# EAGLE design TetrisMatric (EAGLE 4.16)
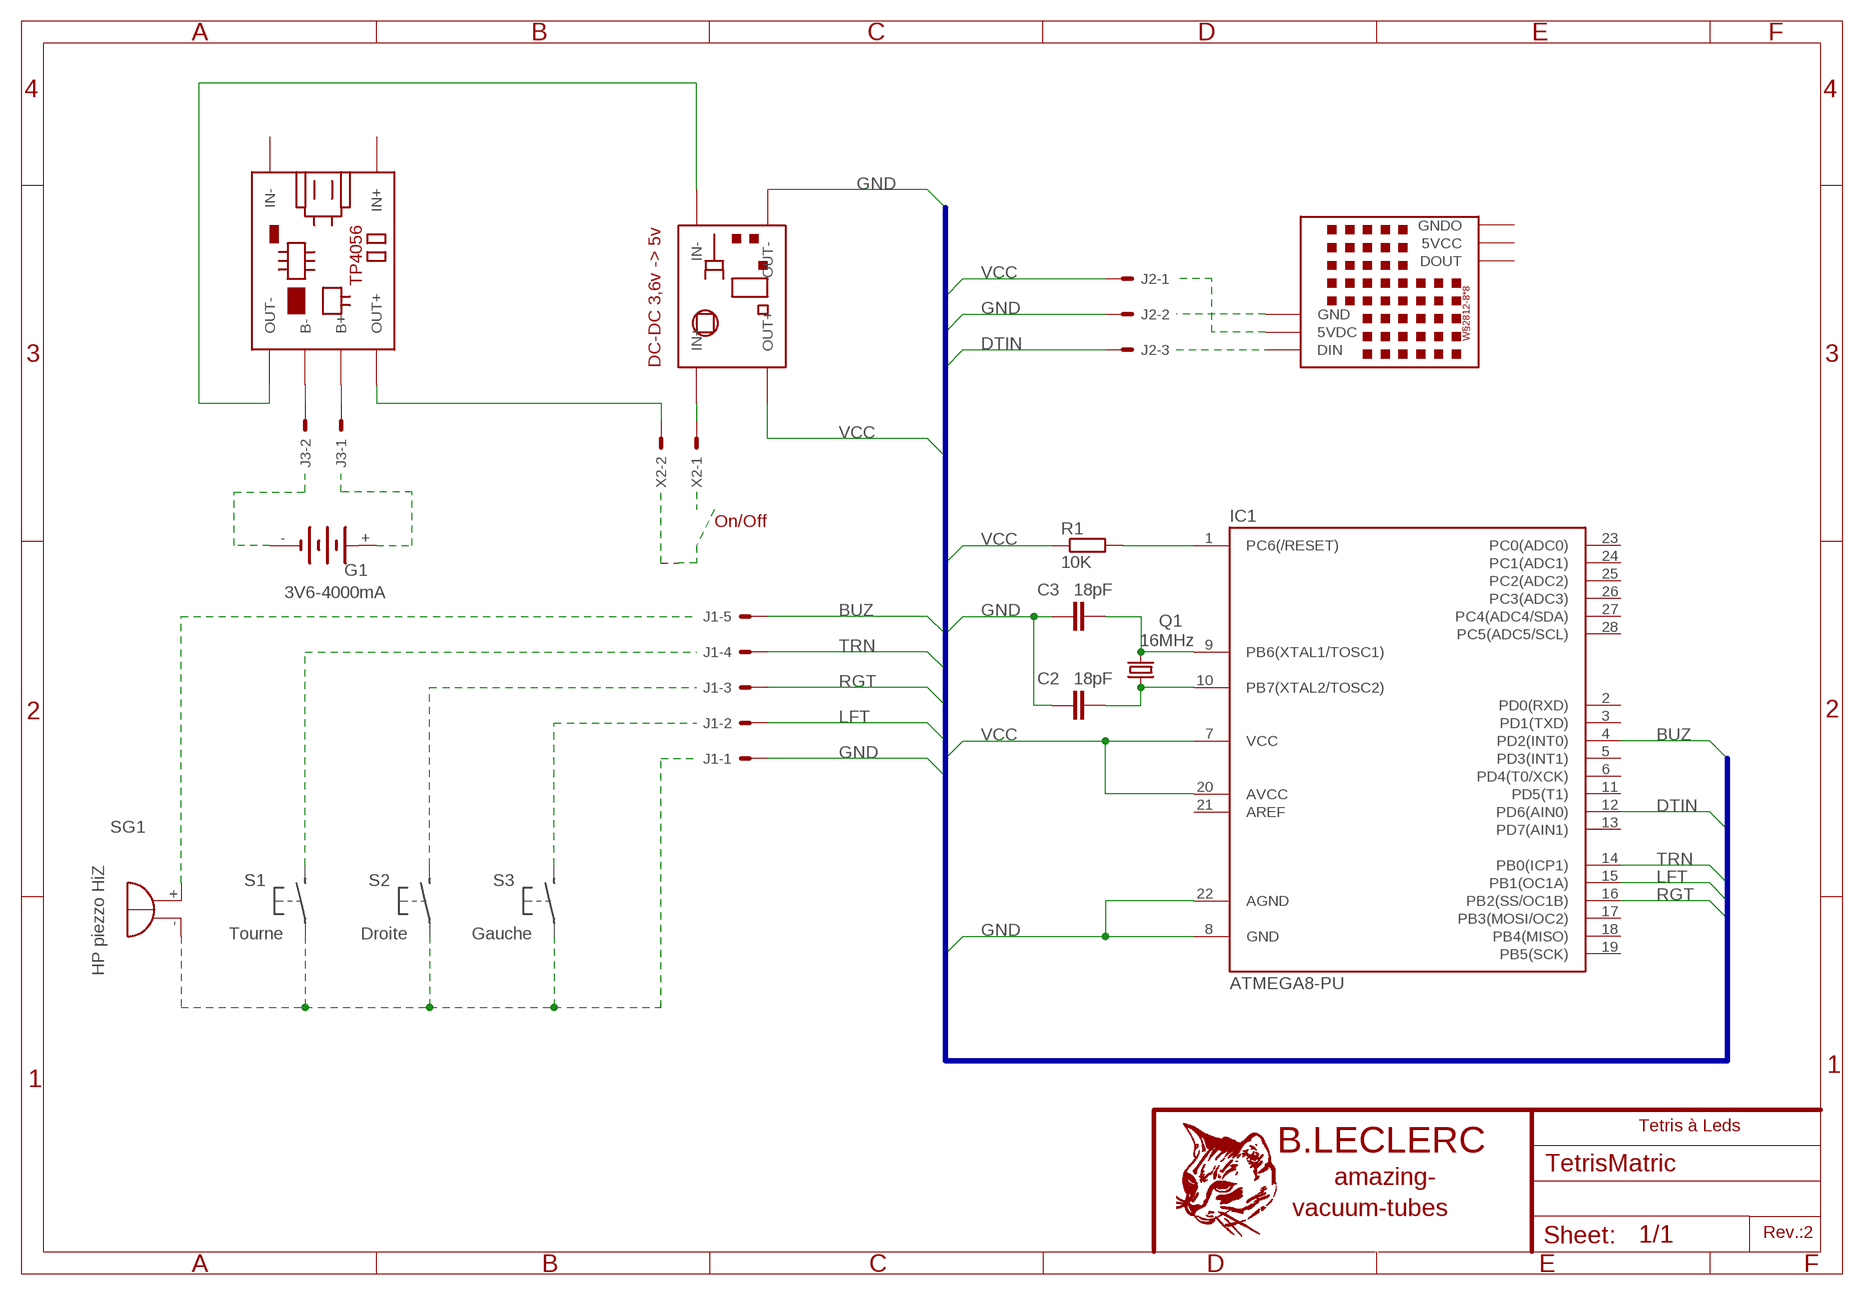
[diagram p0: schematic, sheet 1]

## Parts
C2  18pF  C-EU025_050-025X075  [C025_050-025X075]
C3  18pF  C-EU025_050-025X075  [C025_050-025X075]
G1  3V6-4000mA  3V11R  [3V11R]
IC1  ATMEGA8-PU  [DIL28-3]
J1  22-27-2051-05  [6410-05]
J2  22-27-2031-03  [6410-03]
J3  22-27-2021-02  [6410-02]
Q1  16MHz  CRYTALHC49S  [HC49/S]
R1  10K  R-EU_0207/12  [0207/12]
SG1  HP piezzo HiZ  F/QMBIII  [F/QMBIII]
U$2  DC-DC_BOOST  [DC-DC_BOOST]
U$3  64_LED_PANEL_2812-88  [64_LED_PANEL_2812-8*8]
U$4  CHARGEUR_ION-LI  [CHARGEUR_ION-LI]
X2  22-23-2021  [22-23-2021]

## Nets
BUZ: IC1.4(PD2(INT0)) J1.5
DTIN: IC1.12(PD6(AIN0)) J2.3
GND: C2.1 C3.1 IC1.8(GND) IC1.22(AGND) J1.1 J2.2 U$2.OUT-
LFT: IC1.15(PB1(OC1A)) J1.2
N$4: G1.-
N$5: G1.+
N$6: U$3.DIN
N$7: U$3.5VDC
N$8: U$3.GND
N$9: IC1.1(PC6(/RESET)) R1.2
N$11: C3.2 IC1.9(PB6(XTAL1/TOSC1)) Q1.2
N$12: C2.2 IC1.10(PB7(XTAL2/TOSC2)) Q1.1
N$13: J3.2 U$4.B-
N$14: SG1.+(-)
N$15: J3.1 U$4.B+
N$16: U$2.IN+ X2.1
N$17: U$4.OUT+ X2.2
N$19: U$2.IN- U$4.OUT-
N$36: SG1.-(+)
RGT: IC1.16(PB2(SS/OC1B)) J1.3
TRN: IC1.14(PB0(ICP1)) J1.4
VCC: IC1.7(VCC) IC1.20(AVCC) J2.1 R1.1 U$2.OUT+
Unconnected: IC1.2(PD0(RXD)) IC1.3(PD1(TXD)) IC1.5(PD3(INT1)) IC1.6(PD4(T0/XCK)) IC1.11(PD5(T1)) IC1.13(PD7(AIN1)) IC1.17(PB3(MOSI/OC2)) IC1.18(PB4(MISO)) IC1.19(PB5(SCK)) IC1.21(AREF) IC1.23(PC0(ADC0)) IC1.24(PC1(ADC1)) IC1.25(PC2(ADC2)) IC1.26(PC3(ADC3)) IC1.27(PC4(ADC4/SDA)) IC1.28(PC5(ADC5/SCL)) U$3.DOUT

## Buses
B$1

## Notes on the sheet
- On/Off
- Tetris à Leds
- Rev.:2

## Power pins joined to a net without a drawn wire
5VCC: U$3.5VCC
GNDO: U$3.GNDO
IN+: U$4.IN+
IN-: U$4.IN-

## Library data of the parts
C2 C3 = rcl:C-EU: CAPACITOR, European symbol
G1 = battery:3V11R: NC ACCU Varta
IC1 = atmega8:ATMEGA8-PU
J1 = con-molex:22-?-05: CONNECTOR wire to board 2.54 mm (.1 inch) pitch header
J2 = con-molex:22-?-03: CONNECTOR wire to board 2.54 mm (.1 inch) pitch header
J3 = con-molex:22-?-02: CONNECTOR
Q1 = crystal:CRYTAL: CRYSTAL
R1 = rcl:R-EU_: RESISTOR, European symbol
SG1 = buzzer:F/QMBIII: BUZZER
U$2 = Arduino:DC-DC_BOOST
U$3 = Arduino:64_LED_PANEL_2812-8*8
U$4 = Arduino:CHARGEUR_ION-LI
X2 = con-molex:22-23-2021: .100" (2.54mm) Center Header - 2 Pin

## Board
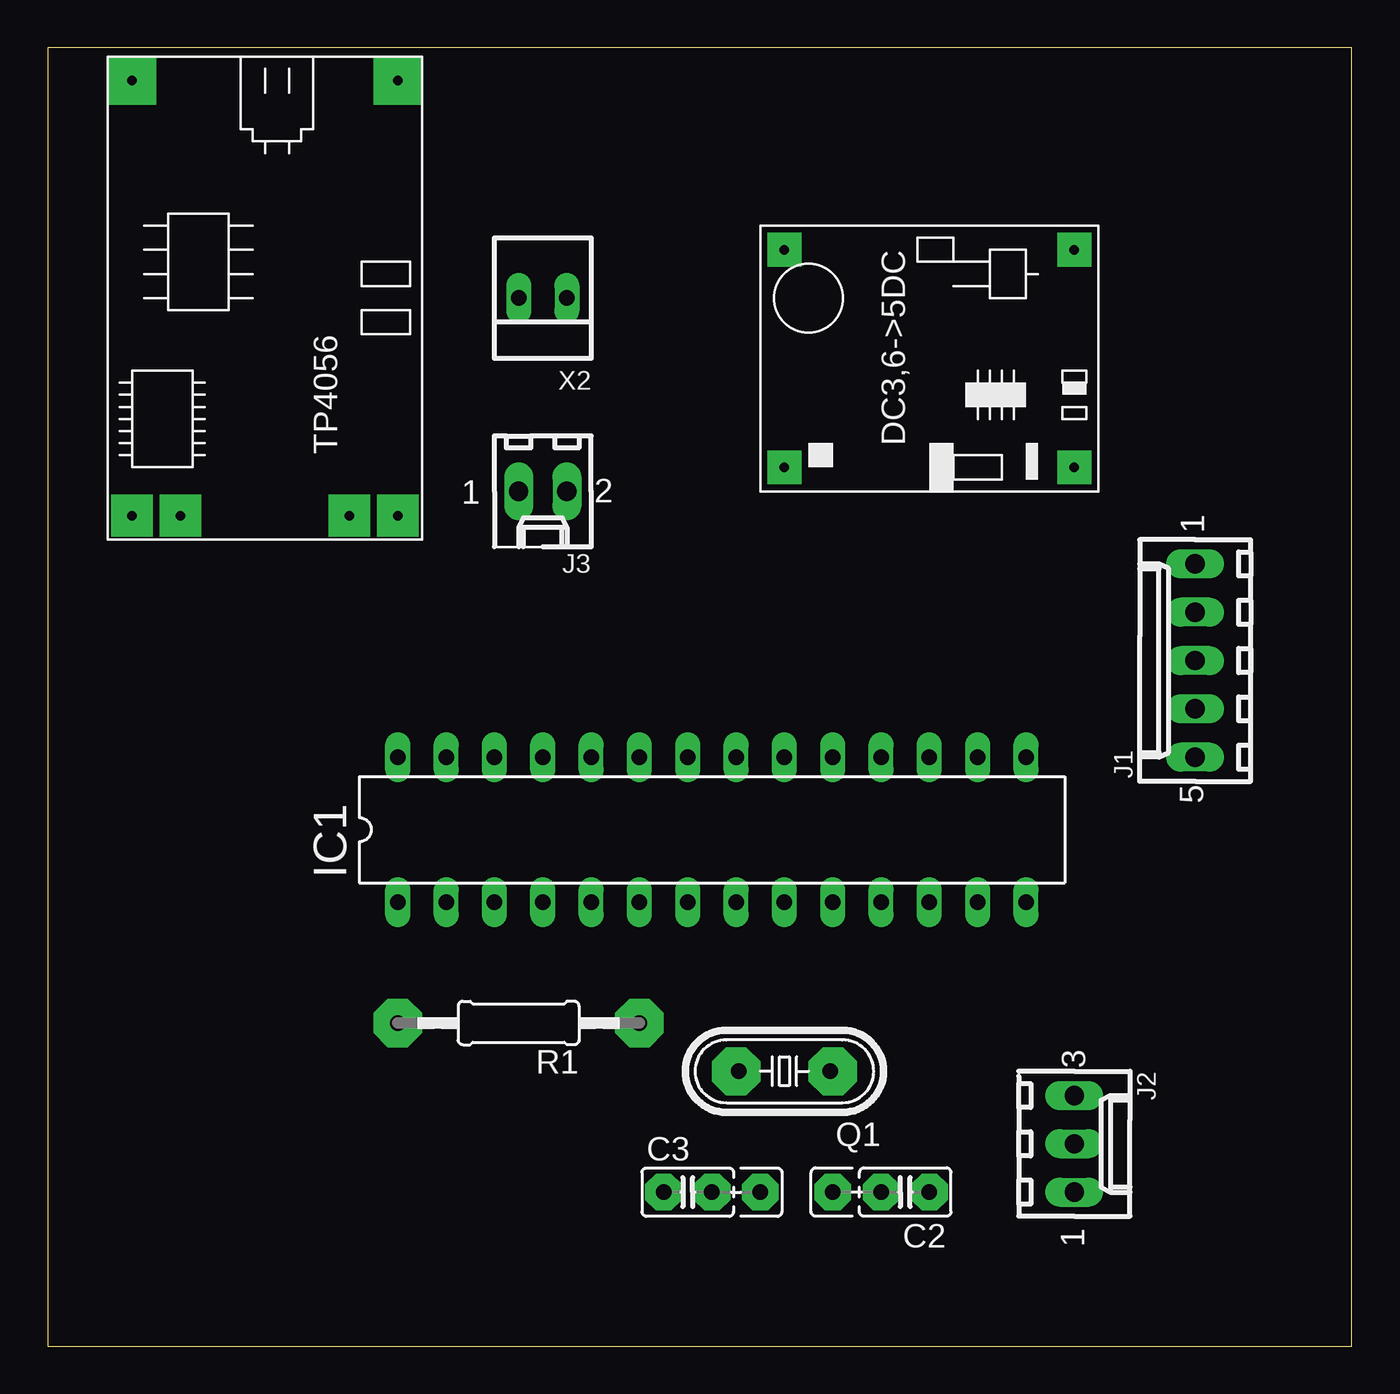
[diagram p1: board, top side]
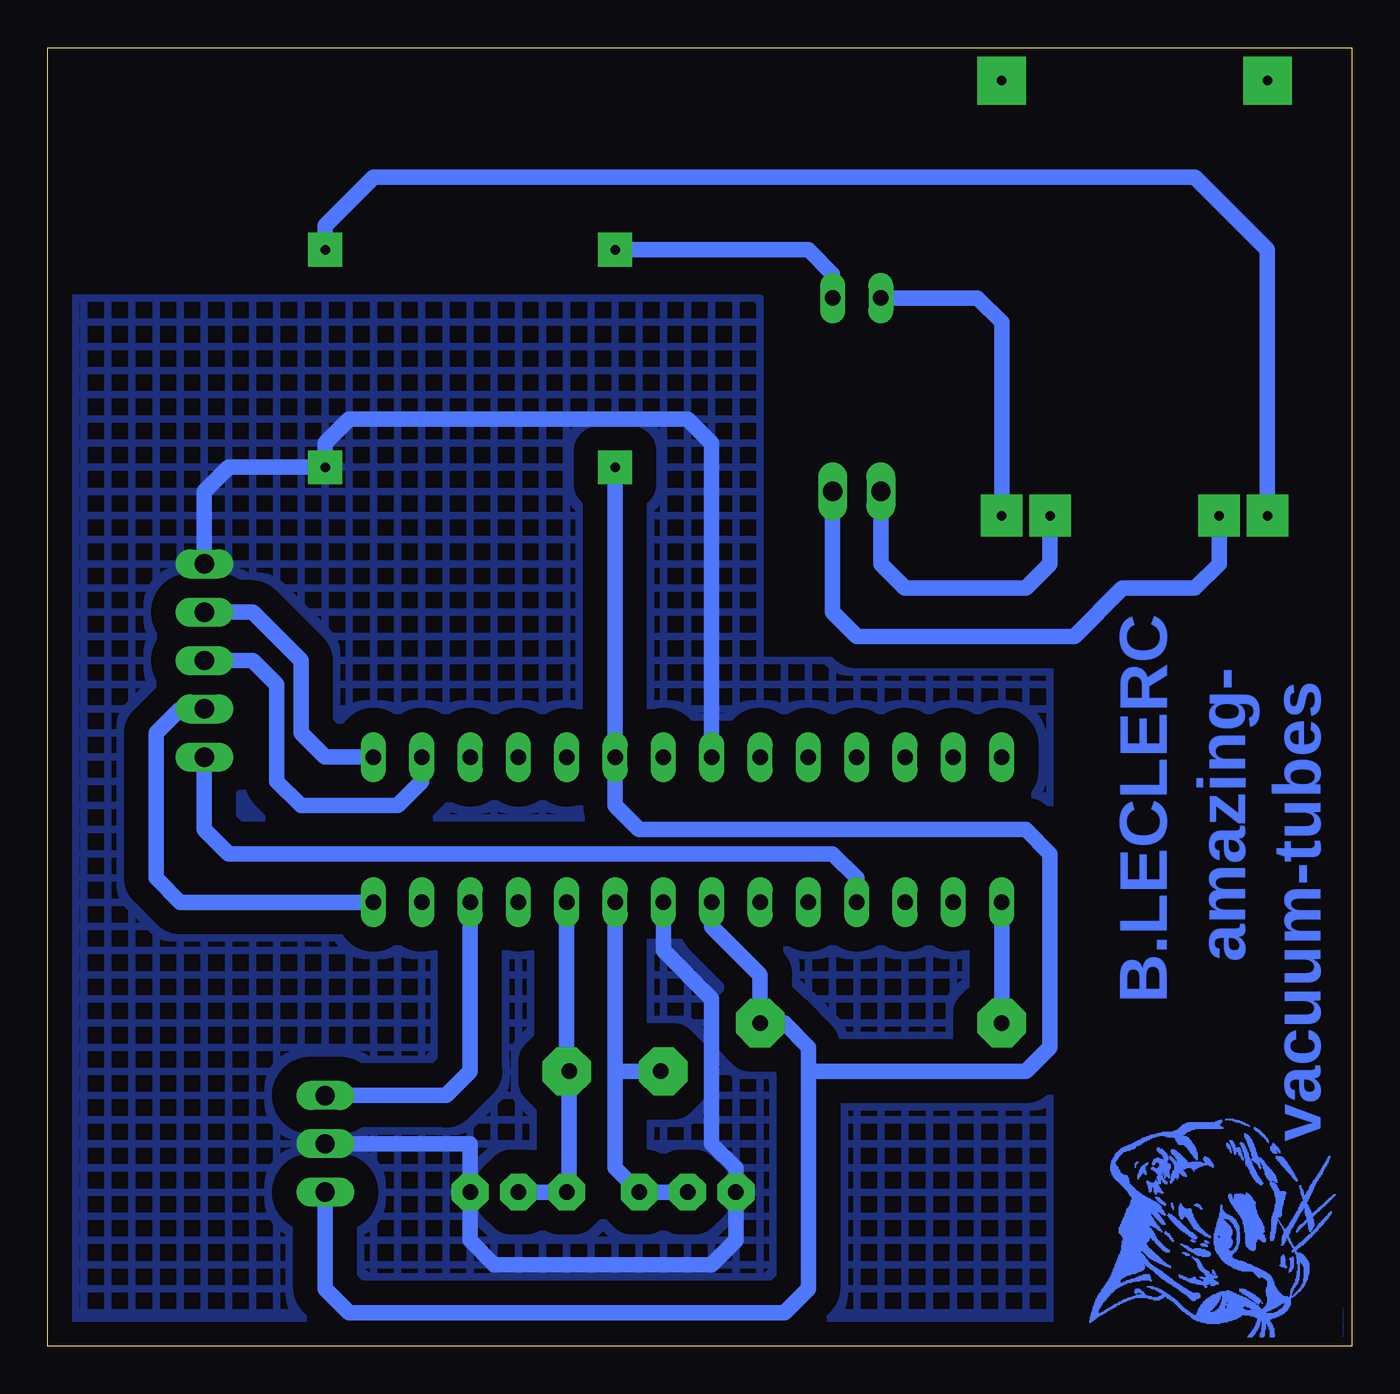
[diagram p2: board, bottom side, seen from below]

Size 68.56 x 68.25 mm. Coordinates in mm from the lower left corner, seen from the top.
Outline: 0,0 68.56,0 68.56,68.25 0,68.25 0,0
Copper layers (1*16): Top 0.035mm / dielectric 1.5mm / Bottom 0.035mm
Design rules "default": minimum track width 10mil, minimum drill 24mil, track to track 8mil, track to pad 8mil, pad to pad 8mil, via to via 8mil, smd to smd 8mil, copper to edge 40mil, drill to drill 8mil, minimum pad ring 10mil, minimum via ring 8mil, stop-mask expansion 4mil, vias tented up to drill 0mil, thermal gap 10mil

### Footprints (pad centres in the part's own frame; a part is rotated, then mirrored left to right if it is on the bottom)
C025_050-025X075 = drill 0.813 octagon: 1 -1.27,0; 2 1.27,0; 3 3.81,0
3V11R = drill 1.118 pad 2.54 octagon: + -5.08,0; - 5.08,0
DIL28-3 = drill 0.813 long: 1 -16.51,-3.81; 2 -13.97,-3.81; 3 -11.43,-3.81; 4 -8.89,-3.81; 5 -6.35,-3.81; 6 -3.81,-3.81; 7 -1.27,-3.81; 8 1.27,-3.81; 9 3.81,-3.81; 10 6.35,-3.81; 11 8.89,-3.81; 12 11.43,-3.81; 13 13.97,-3.81; 14 16.51,-3.81; 15 16.51,3.81; 16 13.97,3.81; 17 11.43,3.81; 18 8.89,3.81; 19 6.35,3.81; 20 3.81,3.81; 21 1.27,3.81; 22 -1.27,3.81; 23 -3.81,3.81; 24 -6.35,3.81; 25 -8.89,3.81; 26 -11.43,3.81; 27 -13.97,3.81; 28 -16.51,3.81
6410-05 = drill 1.016 long: 1 5.08,0; 2 2.54,0; 3 0,0; 4 -2.54,0; 5 -5.08,0
6410-03 = drill 1.016 long: 1 2.54,0; 2 0,0; 3 -2.54,0
6410-02 = drill 1.016 long: 1 1.27,0; 2 -1.27,0
HC49/S = drill 0.813 round: 1 -2.413,0; 2 2.413,0
0207/12 = drill 0.813 octagon: 1 -6.35,0; 2 6.35,0
F/QMBIII = drill 0.914 pad 2.159 octagon: + 3.251,0; - -3.251,0
DC-DC_BOOST = drill 0.5 pad 1.778 square: IN+ 0,0; IN- 0,15.24; OUT+ 11.43,0; OUT- 11.43,15.24
64_LED_PANEL_2812-8*8 = drill 0.5 pad 1.93 long: 5VCC 13.97,0; 5VDC 0,0; DIN 0,2.54; DOUT 13.97,2.54; GND 0,-2.54; GNDO 13.97,-2.54
CHARGEUR_ION-LI = drill 0.5 pad 2.184 square: B+ 24.13,12.7; B- 24.13,3.81; OUT+ 24.13,15.24; OUT- 24.13,1.27 | drill 0.5 pad 2.54 square: IN+ 1.27,15.24; IN- 1.27,1.27
22-23-2021 = drill 0.813 long: 1 -1.27,0; 2 1.27,0

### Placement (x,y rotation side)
C2  45.08,8.09 180 top
C3  33.65,8.09 0 top
G1  not placed on the board
IC1  34.92,27.14 0 top
J1  60.32,36.03 90 top
J2  53.97,10.63 270 top
J3  26.03,44.92 180 top
Q1  38.73,14.44 180 top
R1  24.76,16.98 180 top
SG1  not placed on the board
U$2  38.73,57.62 270 top
U$3  not placed on the board
U$4  3.17,67.78 270 top
U$5  [CHAT1]  0.63,0.47 90 bottom
X2  26.03,55.08 180 top

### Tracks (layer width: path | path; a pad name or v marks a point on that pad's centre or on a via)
BUZ
  Bottom 0.813: IC1.4 26.03,24.6 27.3,25.87 59.05,25.87 60.32,27.14 J1.5
DTIN
  Bottom 0.813: IC1.12 46.35,14.44 47.62,13.17 J2.3
GND  (via drill 0.5 pad 1.27, 0.5 pad 1.93)
  Bottom 0.813: J1.1 60.32,44.92 59.05,46.19 U$2.OUT- 53.97,47.46 52.7,48.73 34.92,48.73 33.65,47.46 IC1.22 | IC1.8 36.19,20.79 33.65,18.25 33.65,10.63 32.38,9.36 C3.1 32.38,5.55 33.65,4.28 45.08,4.28 46.35,5.55 C2.1 46.35,10.63 J2.2
  other vias: 60.32,41.11 53.97,10.63 32.38,8.09 46.35,8.09
  pour Bottom (isolate 1.27, no thermals, hatched): 15.87,0.47 15.87,36.03 31.11,36.03 31.11,55.08 67.94,55.08 67.94,0.47
LFT
  Bottom 0.813: J1.2 57.78,38.57 55.24,36.03 55.24,32.22 53.97,30.95 IC1.15
N$9
  Bottom 0.813: R1.2 IC1.1
N$11
  Bottom 0.813: 38.73,14.44 38.73,9.36 37.46,8.09 C3.2 | 38.73,14.44 IC1.9 | 38.73,14.44 Q1.2
N$12
  Bottom 0.813: IC1.10 41.27,14.44 Q1.1 41.14,8.22 41.27,8.09 C2.2
N$13
  Bottom 0.813: U$4.B- 6.98,41.11 8.25,39.84 12.06,39.84 14.6,37.3 26.03,37.3 27.3,38.57 J3.2
N$15
  Bottom 0.813: U$4.B+ 15.87,41.11 17.14,39.84 23.49,39.84 24.76,41.11 J3.1
N$16
  Bottom 0.813: U$2.IN+ 28.57,57.62 27.3,56.35 X2.1
N$17
  Bottom 0.813: U$4.OUT+ 18.41,53.81 19.68,55.08 X2.2
N$19
  Bottom 0.813: U$4.OUT- 4.44,57.62 8.25,61.43 51.43,61.43 53.97,58.89 U$2.IN-
N$22  (via drill 0.5 pad 2.54)
  other vias: 18.41,16.98
N$24  (via drill 0.5 pad 2.54)
  other vias: 31.11,16.98
N$25  (via drill 0.5 pad 2.54)
  other vias: 36.19,14.44
N$26  (via drill 0.5 pad 2.54)
  other vias: 41.27,14.44
N$28  (via drill 0.5 pad 1.93)
  other vias: 34.92,8.09
N$29  (via drill 0.5 pad 1.93)
  other vias: 37.46,8.09
N$30  (via drill 0.5 pad 1.93)
  other vias: 41.27,8.09
N$31  (via drill 0.5 pad 1.93)
  other vias: 43.81,8.09
N$33  (via drill 0.5 pad 1.27)
  other vias: 20.95,23.33
N$34  (via drill 0.5 pad 1.27)
  other vias: 60.32,38.57
N$35  (via drill 0.5 pad 1.27)
  other vias: 60.32,36.03
N$37  (via drill 0.5 pad 1.27)
  other vias: 60.32,33.49
N$38  (via drill 0.5 pad 1.27)
  other vias: 60.32,30.95
N$40  (via drill 0.5 pad 1.27)
  other vias: 53.97,13.17
N$41  (via drill 0.5 pad 1.27)
  other vias: 23.49,23.33
N$42  (via drill 0.5 pad 1.27)
  other vias: 53.97,8.09
N$43  (via drill 0.5 pad 1.27)
  other vias: 24.76,55.08
N$44  (via drill 0.5 pad 1.27)
  other vias: 24.76,44.92
N$45  (via drill 0.5 pad 1.27)
  other vias: 27.3,55.08
N$46  (via drill 0.5 pad 1.27)
  other vias: 27.3,44.92
N$47  (via drill 0.5 pad 1.27)
  other vias: 31.11,23.33
N$48  (via drill 0.5 pad 1.27)
  other vias: 33.65,23.33
N$49  (via drill 0.5 pad 1.27)
  other vias: 41.27,23.33
N$50  (via drill 0.5 pad 1.27)
  other vias: 46.35,23.33
N$51  (via drill 0.5 pad 1.27)
  other vias: 51.43,23.33
N$52  (via drill 0.5 pad 1.27)
  other vias: 48.89,30.95
N$53  (via drill 0.5 pad 1.27)
  other vias: 43.81,30.95
N$54  (via drill 0.5 pad 1.27)
  other vias: 38.73,30.95
N$55  (via drill 0.5 pad 1.27)
  other vias: 36.19,30.95
N$56  (via drill 0.5 pad 1.27)
  other vias: 33.65,30.95
N$57  (via drill 0.5 pad 1.27)
  other vias: 41.27,30.95
N$58  (via drill 0.5 pad 1.27)
  other vias: 46.35,30.95
N$59  (via drill 0.5 pad 1.27)
  other vias: 51.43,30.95
N$60  (via drill 0.5 pad 1.27)
  other vias: 48.89,23.33
N$61  (via drill 0.5 pad 1.27)
  other vias: 43.81,23.33
N$62  (via drill 0.5 pad 1.27)
  other vias: 38.73,23.33
N$63  (via drill 0.5 pad 1.27)
  other vias: 36.19,23.33
N$64  (via drill 0.5 pad 1.27)
  other vias: 28.57,23.33
N$65  (via drill 0.5 pad 1.27)
  other vias: 26.03,23.33
N$66  (via drill 0.5 pad 1.27)
  other vias: 18.41,23.33
N$69  (via drill 0.5 pad 1.27)
  other vias: 31.11,30.95
N$70  (via drill 0.5 pad 1.27)
  other vias: 28.57,30.95
N$71  (via drill 0.5 pad 1.27)
  other vias: 26.03,30.95
N$72  (via drill 0.5 pad 1.27)
  other vias: 23.49,30.95
N$73  (via drill 0.5 pad 1.27)
  other vias: 20.95,30.95
N$74  (via drill 0.5 pad 1.27)
  other vias: 18.41,30.95
RGT
  Bottom 0.813: J1.3 57.78,36.03 56.51,34.76 56.51,29.68 55.24,28.41 50.16,28.41 48.89,29.68 IC1.16
TRN
  Bottom 0.813: IC1.14 61.59,23.33 62.86,24.6 62.86,32.22 61.59,33.49 J1.4
VCC
  Bottom 0.813: IC1.20 U$2.OUT+ IC1.20 | IC1.7 33.65,22.06 31.11,19.52 R1.1 29.84,16.98 28.57,15.71 28.57,14.44 | 28.57,14.44 28.57,3.01 29.84,1.74 52.7,1.74 53.97,3.01 J2.1 | IC1.20 38.73,28.41 37.46,27.14 17.14,27.14 15.87,25.87 15.87,15.71 17.14,14.44 28.57,14.44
